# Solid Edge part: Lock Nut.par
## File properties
Author: Deepak Maini
Template: normal.par
Last saved by: CADCIM
Revision: 5
Application: Solid Edge
Accuracy: 0.99
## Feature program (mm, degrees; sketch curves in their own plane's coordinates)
sketch for "unnamed Protrusion 1" plane through (0, 0, 0) normal (0, 0, 1) x-axis (1, 0, 0)
  line (-7.5, 12.9904) -> (-15, 0)
  line (-15, 0) -> (-7.5, -12.9904)
  line (-7.5, -12.9904) -> (7.5, -12.9904)
  line (7.5, -12.9904) -> (15, 0)
  line (15, 0) -> (7.5, 12.9904)
  line (7.5, 12.9904) -> (-7.5, 12.9904)
extrude "unnamed Protrusion 1" add finite 8 symmetric
sketch for "unnamed RevolvedCutout 1" plane through (0, 0, 0) normal (0, -1, 0) x-axis (1, 0, 0)
  arc centre (12, 1) radius 3 from (12, 4) to (15, 1) cw
  line (15, 4) -> (15, 1)
  line (15, 4) -> (12, 4)
revolve "unnamed RevolvedCutout 1" cut full turn 360 deg
mirror "unnamed Mirror 1" of "unnamed RevolvedCutout 1" about plane through (0, 0, 0) normal (0, 0, 1)
revolve "unnamed RevolvedCutout 2" cut full turn 360 deg
sketch for "Hole_1" plane through (0, 0, 4) normal (0, 0, 1) x-axis (0, 1, 0)
  hole centre (0, 0) bore radius 6
hole "Hole_1" diameter 12 through
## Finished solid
Body 1: solid body, 11 faces, 22 edges, 12 vertices.
  Faces by surface: plane 8, torus 2, cylinder 1
  Edges by curve: intersection 12, line 6, circle 4
Bounding box of the edges (mm; curved faces can reach further): 30.000 x 25.981 x 8.000, from (-15, -12.9904, -4) to (15, 12.9904, 4).
Cylindrical faces by radius (mm): R6 x1
Toroidal faces (ring radius, tube radius in mm): R12 r3 x2
Planar faces by outward normal: +y 1, +z 1, -y 1, -z 1, oblique 4
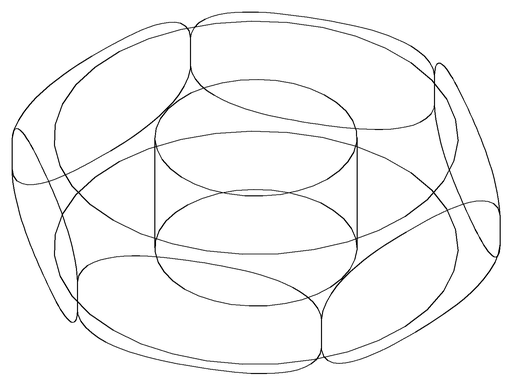
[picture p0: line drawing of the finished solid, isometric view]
